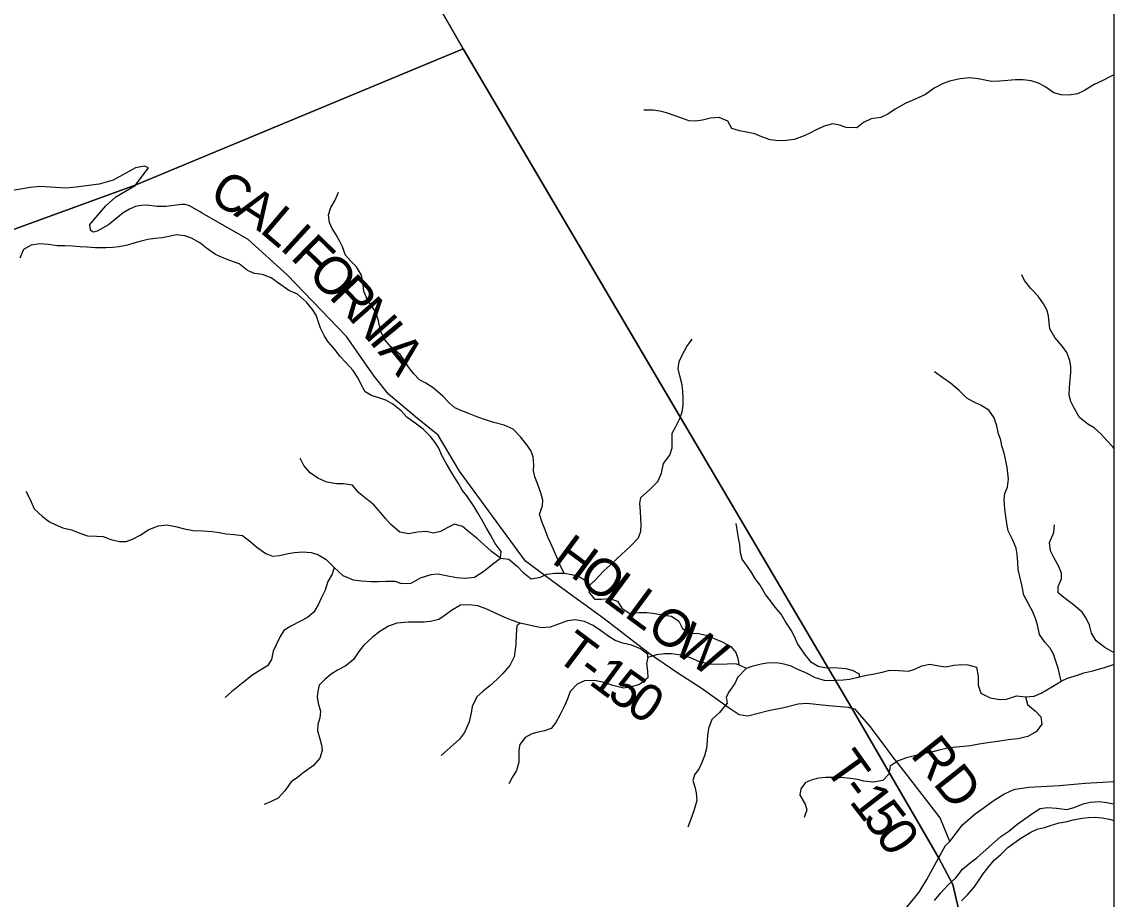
# Model space of a CAD drawing. Extents: x -139 to 835, y 0 to 440.
# Drawn here: x 550 to 607.6, y 344.5 to 390.7 of the extents above; entities that cross this region are included whole.
import ezdxf

# ---------------------------------------------------------------- set-up
doc = ezdxf.new("R2010")
doc.units = 0
for name, color, linetype in [('Default', 7, 'Continuous'), ('GM_X_Major_River', 7, 'Continuous'), ('GM_X_Minor_River', 7, 'Continuous'), ('GM_X_Township_Road', 7, 'Continuous'), ('GM_X_Township_Road_Text', 7, 'Continuous'), ('GM_X_US_Route', 7, 'Continuous'), ('SH_Cut_Line', 7, 'Continuous')]:
    doc.layers.add(name, color=color, linetype=linetype)

msp = doc.modelspace()

# ---------------------------------------------------------------- linework, layer by layer
at = {"layer": 'Default'}
for points in [[(544.238, 377.806), (556.01, 382.105), (573.292, 389.29), (567.097, 400.079), (373.24, 400.079)], [(533.705, 218.461), (553.865, 217.083), (607.596, 213.413), (607.596, 313.688), (599.523, 343.435), (599.103, 345.232), (598.348, 346.669), (593.771, 354.537), (573.292, 389.29), (556.01, 382.105), (544.238, 377.806)]]:
    msp.add_lwpolyline(points, dxfattribs=at)
msp.add_lwpolyline([(607.596, 313.688), (607.596, 400.079), (567.097, 400.079), (573.292, 389.29), (593.771, 354.537), (598.348, 346.669), (599.103, 345.232), (599.523, 343.435)], close=True, dxfattribs=at)
at = {"layer": 'GM_X_Major_River'}
for points in [[(598.138, 344.398), (598.47, 344.801), (598.828, 345.205), (599.251, 345.595), (599.61, 346.047), (600.006, 346.378), (600.362, 346.649), (601.169, 347.371), (601.631, 347.773), (602.04, 348.056), (602.475, 348.399), (602.897, 348.694), (603.372, 349.024), (603.701, 349.236), (604.093, 349.303), (604.562, 349.261), (605.109, 349.183), (605.489, 349.298), (605.962, 349.497), (606.328, 349.576), (606.824, 349.606), (607.215, 349.554), (607.553, 349.49), (607.596, 349.477)], [(599.546, 344.369), (599.877, 344.7), (600.223, 345.104), (600.476, 345.485), (600.689, 345.806), (601.008, 346.198), (601.3, 346.53), (601.631, 346.826), (601.988, 347.194), (602.317, 347.417), (602.687, 347.677), (603.2, 347.995), (603.541, 348.146), (603.921, 348.25), (604.249, 348.354), (604.694, 348.492), (605.113, 348.559), (605.44, 348.639), (605.911, 348.73), (606.251, 348.774), (606.616, 348.781), (606.968, 348.753), (607.332, 348.677), (607.596, 348.607)]]:
    msp.add_lwpolyline(points, dxfattribs=at)
at = {"layer": 'GM_X_Minor_River'}
for points in [[(607.596, 387.909), (607.408, 387.82), (606.961, 387.598), (606.541, 387.399), (606.041, 387.093), (605.66, 386.918)], [(605.66, 386.918), (605.228, 386.851), (604.811, 386.868), (604.421, 386.968), (603.943, 387.298), (603.607, 387.47), (603.217, 387.606), (602.801, 387.659), (602.383, 387.652), (601.991, 387.621), (601.547, 387.578), (601.129, 387.559), (600.427, 387.712), (599.997, 387.753), (599.488, 387.711), (598.925, 387.586), (598.545, 387.447), (598.111, 387.212), (597.649, 386.882), (597.084, 386.613), (596.625, 386.426), (596.059, 386.109), (595.664, 385.838), (595.296, 385.663), (594.787, 385.597), (594.392, 385.398), (594.036, 385.126), (593.475, 385.145), (593.125, 385.257), (592.774, 385.333), (592.368, 385.23), (591.935, 385.043), (591.527, 384.832), (591.172, 384.657), (590.74, 384.506), (590.321, 384.451), (589.93, 384.432), (589.474, 384.485), (589.033, 384.647), (588.67, 384.807), (588.227, 384.896), (587.85, 384.961), (587.46, 385.085), (587.244, 385.472), (586.778, 385.669), (586.334, 385.638), (585.914, 385.524), (585.535, 385.468), (585.197, 385.496), (584.859, 385.608), (584.522, 385.732), (584.015, 385.906), (583.664, 385.994), (583.313, 386.059), (582.817, 386.053)], [(578.613, 361.65), (578.41, 362.048), (578.284, 362.362), (578.057, 362.904), (577.918, 363.206), (577.766, 363.543), (577.615, 363.929), (577.451, 364.327), (577.327, 364.76), (577.477, 365.19), (577.495, 365.501), (577.396, 365.874), (577.233, 366.32), (577.069, 366.718), (577.008, 367.042), (577.013, 367.366), (576.98, 367.774), (576.854, 368.111), (576.65, 368.414), (576.317, 368.837), (575.932, 369.238), (575.452, 369.447), (574.919, 369.598), (574.478, 369.723), (574.062, 369.872), (573.634, 370.045), (573.232, 370.206), (572.856, 370.366), (572.521, 370.658), (572.226, 370.986), (571.724, 371.423), (571.336, 371.656), (570.999, 371.84), (570.678, 372.18), (570.435, 372.482), (570.205, 372.833), (569.975, 373.171), (569.485, 373.585), (569.165, 373.949), (568.975, 374.359), (568.888, 374.684), (568.815, 375.044), (568.665, 375.454), (568.384, 375.877), (568.18, 376.215), (568.067, 376.516), (568.009, 376.997), (567.936, 377.357), (567.668, 377.792), (567.373, 378.096), (567.09, 378.411), (566.94, 378.857), (566.775, 379.158), (566.597, 379.484), (566.393, 379.823), (566.254, 380.136), (566.208, 380.532), (566.331, 380.927), (566.546, 381.308), (566.721, 381.738)], [(575.271, 362.446), (575.29, 362.794), (574.983, 363.205), (574.728, 363.664), (574.525, 364.026), (574.334, 364.364), (574.067, 364.823), (573.863, 365.185), (573.493, 365.717), (573.236, 366.02), (573.046, 366.37), (572.804, 366.757), (572.587, 367.108), (572.409, 367.445), (572.18, 367.856), (572.016, 368.23), (571.825, 368.544), (571.569, 368.859), (571.183, 369.235), (570.693, 369.613), (570.331, 369.869), (570.023, 370.197), (569.585, 370.55), (569.222, 370.77), (568.846, 370.894), (568.469, 371.007), (568.133, 371.215), (567.904, 371.625), (567.765, 371.927), (567.497, 372.326), (567.138, 372.738), (566.804, 373.09), (566.548, 373.417), (566.176, 373.841), (565.997, 374.143), (565.782, 374.565), (565.557, 375.24), (565.366, 375.554), (565.045, 375.941), (564.569, 376.355), (564.115, 376.552), (563.559, 376.931), (563.172, 377.223), (562.718, 377.397), (562.301, 377.438), (561.926, 377.61), (561.5, 377.951), (560.994, 378.137), (560.592, 378.286), (560.255, 378.446), (559.777, 378.775), (559.416, 379.055), (558.989, 379.312), (558.626, 379.437), (558.17, 379.49), (557.79, 379.399), (557.437, 379.331), (557.071, 379.288), (556.679, 379.232), (556.339, 379.153), (555.946, 379.049), (555.618, 378.945), (555.173, 378.843), (554.846, 378.811), (554.468, 378.791), (553.92, 378.798), (553.464, 378.827), (553.125, 378.844), (552.708, 378.885), (552.317, 378.901), (551.913, 378.906), (551.457, 378.972), (550.975, 379.002), (550.543, 378.935), (550.136, 378.712), (549.933, 378.247)], [(607.596, 368.214), (607.502, 368.319), (607.194, 368.658), (606.911, 368.973), (606.551, 369.313), (606.215, 369.509), (605.776, 369.85), (605.471, 370.382), (605.306, 370.696), (605.232, 371.032), (605.238, 371.416), (605.27, 371.859), (605.315, 372.231), (605.319, 372.53), (605.259, 372.855), (605.109, 373.288), (604.878, 373.603), (604.468, 374.064), (604.214, 374.534), (604.166, 374.847), (604.132, 375.207), (604.046, 375.532), (603.867, 375.846), (603.586, 376.257), (603.201, 376.657), (602.881, 377.081), (602.729, 377.382)], [(579.881, 360.951), (580.251, 361.283), (580.688, 361.745), (581.072, 362.112), (581.403, 362.42), (582.103, 363.047), (582.527, 363.51), (582.65, 363.856), (582.668, 364.216), (582.659, 364.516), (582.639, 364.912), (582.606, 365.32), (582.663, 365.631), (583.112, 366.045), (583.549, 366.484), (583.751, 366.925), (583.85, 367.427), (584.182, 367.867), (584.305, 368.249), (584.317, 369.029), (584.505, 369.386), (584.706, 369.804), (584.829, 370.15), (584.886, 370.485), (584.892, 370.869), (584.871, 371.217), (584.837, 371.577), (584.713, 372.046), (584.627, 372.419), (584.672, 372.814), (584.834, 373.148), (585.088, 373.589), (585.355, 373.981)], [(604.803, 355.963), (604.718, 356.335), (604.644, 356.636), (604.544, 356.961), (604.407, 357.382), (604.216, 357.696), (603.946, 358.011), (603.665, 358.411), (603.555, 358.928), (603.456, 359.265), (603.317, 359.614), (603.089, 360.037), (602.835, 360.495), (602.75, 360.952), (602.627, 361.469), (602.541, 361.842), (602.52, 362.214), (602.488, 362.646), (602.44, 362.958), (602.25, 363.381), (602.01, 363.875), (601.937, 364.26), (601.89, 364.632), (601.844, 365.028), (601.799, 365.545), (601.843, 365.856), (601.978, 366.19), (602.023, 366.597), (602.002, 366.921), (601.954, 367.222), (601.869, 367.655), (601.796, 367.967), (601.684, 368.352), (601.623, 368.653), (601.51, 368.99), (601.412, 369.423), (601.275, 369.844), (600.994, 370.244), (600.593, 370.488), (600.191, 370.685), (599.842, 370.869), (599.43, 371.27), (598.979, 371.659), (598.566, 371.952), (598.127, 372.269)], [(575.271, 362.446), (574.794, 362.788), (574.382, 363.152), (574.034, 363.48), (573.596, 363.833), (573.261, 364.113), (572.832, 364.238), (572.451, 364.039), (572.109, 363.839), (571.742, 363.748), (571.352, 363.836), (570.882, 363.818), (570.424, 363.716), (569.956, 363.817), (569.479, 364.219), (569.21, 364.522), (568.966, 364.837), (568.594, 365.249), (568.246, 365.529), (567.807, 365.882), (567.461, 366.282), (566.966, 366.36), (566.627, 366.364), (566.107, 366.442), (565.64, 366.652), (565.227, 366.945), (564.906, 367.332), (564.703, 367.718)], [(550.262, 365.962), (550.491, 365.54), (550.693, 365.045), (551.13, 364.644), (551.504, 364.352), (551.841, 364.192), (552.204, 364.044), (552.659, 363.93), (553.152, 363.745), (553.503, 363.608), (553.985, 363.591), (554.324, 363.574), (554.739, 363.426), (555.194, 363.312), (555.533, 363.32), (555.874, 363.436), (556.282, 363.647), (556.743, 363.953), (557.241, 364.139), (557.686, 364.193), (558.141, 364.104), (558.622, 363.99), (559.077, 363.889), (559.56, 363.883), (560.068, 363.853), (560.445, 363.788), (560.81, 363.724), (561.213, 363.683), (561.669, 363.63), (562.056, 363.337), (562.43, 363.021), (562.895, 362.679), (563.258, 362.543), (563.611, 362.587), (564.069, 362.689), (564.409, 362.733), (564.84, 362.776), (565.296, 362.746), (565.647, 362.634), (566.073, 362.365), (566.498, 361.952), (566.961, 361.527), (567.493, 361.305), (567.936, 361.251), (568.444, 361.209), (568.822, 361.217), (569.214, 361.224), (569.696, 361.218), (570.047, 361.106), (570.556, 361.124), (571.042, 361.394), (571.606, 361.579), (571.972, 361.61), (572.401, 361.533), (572.948, 361.419), (573.403, 361.377), (573.9, 361.443), (574.387, 361.749), (574.849, 362.115), (575.271, 362.446), (575.701, 362.393), (576.152, 362.004), (576.448, 361.7), (576.886, 361.347), (577.37, 361.437), (577.699, 361.589), (578.13, 361.656), (578.613, 361.65), (579.029, 361.585), (579.431, 361.448), (579.781, 361.252), (579.881, 360.951), (579.928, 360.627), (580.223, 360.276), (580.562, 360.283), (581.007, 360.314), (581.435, 360.177), (581.664, 359.802), (582.078, 359.522), (582.561, 359.576), (582.965, 359.571), (583.421, 359.517), (583.864, 359.44), (584.28, 359.375), (584.655, 359.119), (584.858, 358.733), (585.259, 358.488), (585.689, 358.471), (586.092, 358.382), (586.52, 358.209), (586.935, 358.036), (587.401, 357.779), (587.67, 357.475), (587.77, 357.174), (587.817, 356.814), (588.232, 356.641), (588.573, 356.769), (588.992, 356.872), (589.319, 356.928), (589.802, 356.934), (590.192, 356.869)], [(594.174, 356.186), (594.177, 356.33), (593.814, 356.526), (593.476, 356.614), (593.033, 356.643), (592.355, 356.652), (592.004, 356.728), (591.655, 356.936), (591.283, 357.396), (590.913, 357.94), (590.748, 358.302), (590.571, 358.652), (590.265, 359.123), (590.048, 359.486), (589.727, 359.849), (589.484, 360.188), (589.228, 360.527), (588.948, 361.01), (588.692, 361.337), (588.463, 361.723), (588.233, 362.062), (588.003, 362.388), (587.917, 362.713), (587.871, 363.158), (587.811, 363.494), (587.739, 363.951), (587.678, 364.275)], [(607.596, 357.461), (607.475, 357.526), (607.099, 357.734), (606.648, 358.087), (606.406, 358.486), (606.295, 358.907), (606.13, 359.269), (605.913, 359.595), (605.449, 359.984), (605.036, 360.289), (604.65, 360.606), (604.642, 360.953), (604.817, 361.347), (604.821, 361.647), (604.67, 362.032), (604.428, 362.431), (604.251, 362.817), (604.193, 363.273), (604.422, 363.798), (604.454, 364.194)], [(566.498, 361.952), (566.388, 361.594), (566.174, 361.201), (566.024, 360.759), (565.809, 360.33), (565.674, 360.007), (565.433, 359.591), (565.103, 359.319), (564.734, 359.119), (564.222, 358.862), (563.84, 358.626), (563.653, 358.317), (563.451, 357.876), (563.289, 357.53), (563.192, 357.099), (562.991, 356.766), (562.636, 356.554), (562.162, 356.248), (561.792, 355.953), (561.449, 355.681), (561.092, 355.386), (560.762, 355.09)], [(583.022, 357.208), (583.025, 357.364), (582.638, 357.668), (582.171, 357.854), (581.703, 357.955), (581.313, 358.104), (580.977, 358.312), (580.538, 358.629), (580.138, 358.897), (579.697, 359.107), (579.19, 359.185), (578.798, 359.141), (578.26, 358.944), (577.88, 358.805), (577.436, 358.774), (577.006, 358.851), (576.304, 359.004), (575.837, 359.165), (575.5, 359.313), (575.098, 359.486), (574.541, 359.745), (574.074, 359.93), (573.592, 359.984), (573.161, 359.965), (572.687, 359.683), (572.345, 359.435), (572.015, 359.211), (571.583, 359.097), (571.243, 359.065), (570.839, 359.07), (570.421, 359.063), (569.807, 359.01), (569.362, 358.848), (568.901, 358.565), (568.505, 358.258), (568.056, 357.856), (567.803, 357.511), (567.523, 357.095), (567.113, 356.764), (566.68, 356.541), (566.337, 356.318), (566.007, 356.046), (565.716, 355.738), (565.633, 355.427), (565.602, 355.127), (565.65, 354.803), (565.774, 354.382), (565.743, 354.022), (565.633, 353.676), (565.629, 353.352), (565.702, 353.039), (565.839, 352.594), (565.874, 352.294), (565.738, 351.9), (565.406, 351.508), (564.918, 351.154), (564.562, 350.883), (564.232, 350.647), (563.899, 350.171), (563.541, 349.78), (563.147, 349.592), (562.806, 349.453)], [(576.304, 359.004), (576.12, 358.874), (576.086, 358.395), (576.066, 357.915), (576.036, 357.616), (575.978, 357.245), (575.763, 356.78), (575.391, 356.352), (575.074, 356.044), (574.703, 355.701), (574.347, 355.429), (574.017, 355.122), (573.774, 354.621), (573.717, 354.286), (573.619, 353.807), (573.363, 353.247), (573.097, 352.902), (572.608, 352.452), (572.132, 352.038)], [(587.817, 356.814), (587.649, 356.864), (587.205, 356.857), (586.774, 356.839), (586.292, 356.856), (585.746, 356.983), (585.279, 357.192), (584.785, 357.33), (584.277, 357.396), (583.925, 357.401), (583.481, 357.346), (583.022, 357.208), (582.952, 356.885), (583.012, 356.488), (583.02, 356.128), (582.584, 355.786), (582.165, 355.659), (581.746, 355.592), (581.187, 355.719), (580.642, 355.905), (580.213, 355.994), (579.691, 355.965), (579.297, 355.801), (578.939, 355.41), (578.776, 354.968), (578.628, 354.658), (578.4, 354.205), (578.171, 353.776), (577.932, 353.467), (577.578, 353.34), (577.251, 353.26), (576.923, 353.18), (576.555, 352.992), (576.276, 352.624), (576.232, 352.313), (576.223, 351.689), (576.099, 351.247), (575.885, 350.878), (575.698, 350.544)], [(590.192, 356.869), (590.569, 356.757), (590.919, 356.585), (591.334, 356.412), (591.839, 356.154), (592.371, 355.992), (592.972, 356.009), (593.311, 356.028), (593.651, 356.06), (594.174, 356.186), (594.541, 356.277), (594.881, 356.333), (595.365, 356.435), (595.771, 356.527), (596.241, 356.521), (596.762, 356.479), (597.103, 356.594), (597.471, 356.77), (597.889, 356.849), (598.357, 356.759), (598.722, 356.719), (599.141, 356.798), (599.546, 356.829), (599.885, 356.813), (600.34, 356.7), (600.437, 356.195), (600.43, 355.739), (600.58, 355.329), (601.072, 355.072), (601.58, 354.994), (601.919, 355.002), (602.457, 355.175), (602.926, 355.133), (603.383, 355.164), (603.751, 355.327), (604.356, 355.68), (604.803, 355.963), (605.132, 356.115), (605.669, 356.276), (605.997, 356.392), (606.468, 356.506), (607.136, 356.702), (607.516, 356.818), (607.596, 356.838)], [(588.232, 356.641), (587.755, 356.143), (587.607, 355.833), (587.314, 355.417), (587.153, 355.107), (587.201, 354.795), (586.802, 354.296), (586.406, 353.941), (586.216, 353.463), (586.172, 353.116), (586.154, 352.817), (586.122, 352.409), (586.012, 352.027), (585.877, 351.669), (585.729, 351.347), (585.489, 351.026), (585.406, 350.715), (585.506, 350.39), (585.579, 350.065), (585.6, 349.669), (585.448, 349.119), (585.285, 348.678), (585.136, 348.26)], [(602.926, 355.133), (603.037, 354.724), (603.45, 354.372), (603.732, 354.068), (603.779, 353.696), (603.499, 353.304), (603.052, 353.045), (602.528, 352.92), (602.006, 352.866), (601.574, 352.799), (600.816, 352.688), (600.384, 352.609), (600.031, 352.554), (599.678, 352.51), (599.26, 352.479), (598.75, 352.401), (598.305, 352.299), (597.978, 352.207), (597.494, 352.129), (597.141, 352.037), (596.656, 351.923), (596.21, 351.748), (595.789, 351.477), (595.73, 351.058), (595.412, 350.726), (594.915, 350.636), (594.407, 350.69), (594.069, 350.778), (593.705, 350.831), (593.171, 350.873), (592.792, 350.878), (592.388, 350.871), (592.035, 350.839), (591.682, 350.759), (591.34, 350.607), (591.088, 350.287), (591.031, 349.94), (591.311, 349.48), (591.398, 349.18), (591.261, 348.773)]]:
    msp.add_lwpolyline(points, dxfattribs=at)
at = {"layer": 'GM_X_Township_Road'}
for points in [[(559.435, 380.696), (558.881, 381.015), (558.654, 381.086), (558.47, 381.073), (557.629, 380.975), (557.166, 380.978), (556.637, 381.041), (556.334, 381.03), (556.04, 380.983), (555.713, 380.831), (555.379, 380.65), (554.605, 380.001), (554.018, 379.68), (553.949, 379.66), (553.826, 379.626), (553.77, 379.645), (553.662, 379.729), (553.657, 379.774), (553.627, 380.029), (554.469, 381.005), (554.996, 381.479), (556.018, 382.088), (556.716, 383.011), (556.505, 383.101), (556.034, 383.011), (554.86, 382.371), (554.117, 382.146), (552.898, 382), (552.366, 381.947), (550.984, 382.023), (550.495, 381.979), (546.894, 381.378)], [(594.188, 354.2), (593.951, 354.471), (593.779, 354.521), (593.606, 354.57), (592.55, 354.649), (591.401, 354.775), (590.94, 354.745), (590.197, 354.557), (589.39, 354.393), (588.288, 354.111), (587.84, 354.181), (587.315, 354.534), (585.842, 355.58), (584.6, 356.379), (583.114, 357.39), (580.732, 359.248), (578.349, 360.964), (576.582, 362.28), (573.098, 367.029), (571.979, 368.928), (570.898, 369.795), (569.368, 371.09), (568.606, 372.028), (567.143, 374.131), (564.015, 377.38), (561.973, 379.236), (559.552, 380.629), (559.435, 380.696)], [(598.938, 347.509), (598.436, 348.743), (596.7, 350.979), (595.989, 351.899), (595.396, 352.71), (594.749, 353.561), (594.188, 354.2)]]:
    msp.add_lwpolyline(points, dxfattribs=at)
at = {"layer": 'GM_X_US_Route'}
for points in [[(598.938, 347.509), (599.611, 348.377), (600.268, 348.961), (600.699, 349.268), (601.217, 349.653), (601.777, 350), (602.144, 350.178), (602.381, 350.267), (603.092, 350.366), (604.72, 350.464), (606.068, 350.573), (607.596, 350.661)], [(549.297, 321.159), (555.655, 323.421), (564.321, 326.564), (572.518, 329.858), (576.454, 331.078), (579.806, 332.38), (582.837, 333.43), (586.404, 334.793), (588.425, 335.666), (590.09, 336.591), (591.084, 337.301), (592.564, 338.477), (593.36, 339.308), (593.991, 340.424), (594.511, 341.356), (594.906, 341.923), (596.447, 343.761), (597.314, 344.835), (597.721, 345.502), (598.356, 346.652), (598.705, 347.289), (598.938, 347.509)]]:
    msp.add_lwpolyline(points, dxfattribs=at)
at = {"layer": 'SH_Cut_Line'}
msp.add_lwpolyline([(607.596, 213.413), (607.596, 400.079), (373.24, 400.079), (373.24, 228.621), (390.412, 227.867), (402.968, 227.036), (407.389, 226.858), (433.728, 225.419), (479.461, 222.215), (494.743, 221.147), (512.652, 220.106), (533.705, 218.461), (553.865, 217.083)], close=True, dxfattribs=at)

# ---------------------------------------------------------------- texts
at = {"layer": 'GM_X_Township_Road_Text'}
for s, height, rotation, p in [('C', 1.936, 329.51481, (559.83, 381.327)), ('A', 1.947, 327.00632, (561.164, 380.543)), ('L', 1.971, 319.66618, (562.518, 379.668)), ('I', 1.976, 317.57039, (563.579, 378.768)), ('F', 1.979, 315.60268, (564.137, 378.259)), ('O', 1.982, 313.95512, (565.03, 377.384)), ('R', 1.982, 313.49346, (566.169, 376.203)), ('N', 1.984, 311.35251, (567.212, 375.103)), ('I', 1.985, 309.62458, (568.286, 373.885)), ('A', 1.985, 309.20964, (568.77, 373.3)), ('H', 1.96, 323.56274, (577.902, 362.239)), ('O', 1.96, 323.56134, (579.245, 361.248)), ('L', 1.96, 323.56578, (580.587, 360.257)), ('L', 1.96, 323.55988, (581.728, 359.415)), ('O', 1.96, 323.62961, (582.872, 358.571)), ('W', 1.955, 325.05633, (584.258, 357.55)), ('T', 1.961, 323.18964, (578.085, 357.169)), ('-', 1.961, 323.26052, (579.22, 356.319)), ('1', 1.96, 323.62772, (579.849, 355.85)), ('5', 1.956, 324.63844, (580.813, 355.141)), ('0', 1.952, 325.72373, (581.792, 354.446)), ('RD', 1.9852, 308.48391, (596.817, 352.062)), ('T', 1.985, 305.52318, (592.286, 351.402)), ('-', 1.985, 306.97249, (593.118, 350.238)), ('1', 1.985, 307.86138, (593.594, 349.607)), ('5', 1.985, 307.78814, (594.294, 348.706)), ('0', 1.984, 303.77561, (594.973, 347.832))]:
    msp.add_text(s, height=height, rotation=rotation, dxfattribs=at).set_placement(p)

doc.saveas('drawing.dxf')
